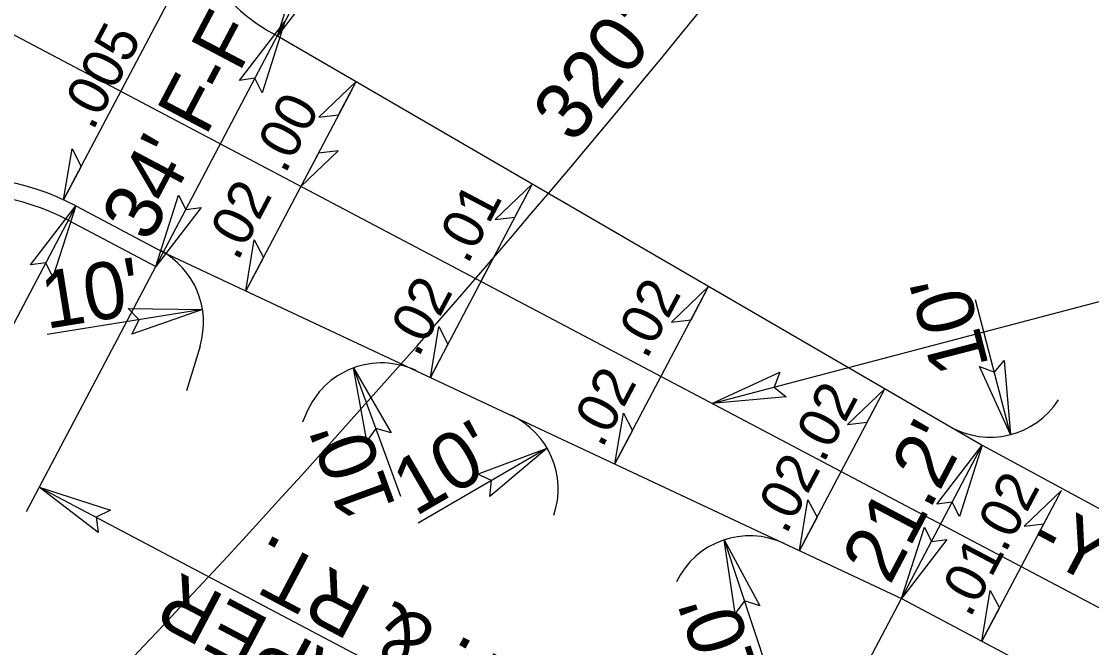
# Model space of a CAD drawing. Extents: x 2010838 to 2015151, y 441905 to 447792.
# Drawn here: x 2014224.3 to 2014355.7, y 445259 to 445335.9 of the extents above; entities that cross this region are included whole.
import ezdxf

# ---------------------------------------------------------------- set-up
doc = ezdxf.new("R2010")
doc.units = 0
for name, color, linetype in [('A-Wall-Blow', 7, 'Continuous'), ('A-Wall-Comp', 7, 'Continuous'), ('C-Building', 7, 'Continuous'), ('C-CURB STOPS', 7, 'Continuous'), ('C-Grave Plots', 7, 'Continuous'), ('CLRD', 7, 'Continuous'), ('Cont-2-Lidar', 7, 'Continuous'), ('DEED', 7, 'Continuous'), ('Default_10ft_LIDAR_Contou', 7, 'Continuous'), ('HATCH', 7, 'Continuous'), ('s-Existing Major', 7, 'Continuous'), ('S-Existing Minor', 7, 'Continuous'), ('S-overhead electric', 7, 'Continuous'), ('TEXT-MED', 7, 'Continuous')]:
    doc.layers.add(name, color=color, linetype=linetype)

msp = doc.modelspace()

# ---------------------------------------------------------------- linework, layer by layer
at = {"layer": 'A-Wall-Blow'}
for p, q in [((2014229.53, 445314), (2014245.5, 445344.26)), ((2014252.46, 445303.88), (2014264.98, 445327.61)), ((2014274.57, 445292.21), (2014287.09, 445315.94)), ((2014297.23, 445281.58), (2014308.73, 445303.38)), ((2014319.88, 445270.95), (2014330.36, 445290.81)), ((2014342.28, 445259.83), (2014352.04, 445278.32))]:
    msp.add_line(p, q, dxfattribs=at)
at = {"layer": 'A-Wall-Comp'}
for points in [[(2014265.45, 445328.51), (2014260.88, 445324.13), (2014263.29, 445324.42)], [(2014229.53, 445314), (2014230.56, 445320.24), (2014231.69, 445318.09)], [(2014258.66, 445315.64), (2014263.23, 445320.01), (2014260.82, 445319.73)], [(2014287.09, 445315.94), (2014282.52, 445311.57), (2014284.93, 445311.85)], [(2014251.91, 445302.84), (2014252.94, 445309.08), (2014254.07, 445306.93)], [(2014308.73, 445303.38), (2014304.16, 445299), (2014306.57, 445299.29)], [(2014274.57, 445292.21), (2014275.6, 445298.45), (2014276.72, 445296.3)], [(2014330.36, 445290.81), (2014325.79, 445286.44), (2014328.2, 445286.72)], [(2014297.23, 445281.58), (2014298.26, 445287.82), (2014299.38, 445285.67)], [(2014352.04, 445278.32), (2014347.47, 445273.94), (2014349.88, 445274.23)], [(2014319.88, 445270.95), (2014320.92, 445277.19), (2014322.04, 445275.04)], [(2014342.28, 445259.83), (2014343.31, 445266.07), (2014344.44, 445263.92)]]:
    msp.add_lwpolyline(points, close=True, dxfattribs=at)
at = {"layer": 'C-Building'}
msp.add_line((2014280.77, 445303.97), (2014283.11, 445308.39), dxfattribs=at)
at = {"layer": 'C-CURB STOPS'}
msp.add_arc((2013223.9, 446217.91), 1292, 312.84627, 322.2051, dxfattribs=at)
msp.add_arc((2013223.9, 446217.91), 1292, 312.84627, 322.2051, dxfattribs=at)
at = {"layer": 'C-Grave Plots'}
for p, q in [((2014345.79, 445285.19), (2014341.51, 445301.74)), ((2014246.59, 445300.55), (2014227.5, 445297.46)), ((2014265.14, 445293.37), (2014270.89, 445277.61)), ((2014288.89, 445283.53), (2014273.05, 445274.31)), ((2014310.65, 445272.27), (2014316.07, 445255.82))]:
    msp.add_line(p, q, dxfattribs=at)
at = {"layer": 'CLRD'}
msp.add_line((2014192.33, 445350.64), (2014369.92, 445256.93), dxfattribs=at)
msp.add_line((2014192.33, 445350.64), (2014369.92, 445256.93), dxfattribs=at)
msp.add_arc((2013223.9, 446217.91), 1300, 266.62643, 322.2051, dxfattribs=at)
at = {"layer": 'DEED'}
msp.add_arc((2013223.9, 446217.91), 1292, 312.84627, 322.2051, dxfattribs=at)
at = {"layer": 'Default_10ft_LIDAR_Contou'}
msp.add_line((2014309.14, 445289), (2014410.5, 445315.67), dxfattribs=at)
at = {"layer": 'HATCH'}
for radius, start in [(1279.25, 293.04012), (1291.25, 312.84627)]:
    msp.add_arc((2013223.9, 446217.91), radius, start, 322.2051, dxfattribs=at)
at = {"layer": 's-Existing Major'}
for points in [[(2014261.35, 445341.36), (2014255.78, 445334.12), (2014258.58, 445342.87), (2014259.46, 445341.11)], [(2014251.14, 445328.66), (2014256.71, 445335.89), (2014253.9, 445327.14), (2014253.02, 445328.91)], [(2014246.41, 445313.06), (2014240.84, 445305.82), (2014243.65, 445314.57), (2014244.53, 445312.81)], [(2014225.45, 445306.03), (2014231.02, 445313.26), (2014228.22, 445304.51), (2014227.34, 445306.28)], [(2014237.45, 445300.65), (2014246.59, 445300.55), (2014237.91, 445297.53), (2014238.79, 445299.29)], [(2014266.77, 445284.39), (2014265.14, 445293.37), (2014269.74, 445285.42), (2014267.85, 445285.95)], [(2014345.03, 445294.29), (2014345.79, 445285.19), (2014341.97, 445293.55), (2014343.81, 445292.84)], [(2014318.24, 445289.8), (2014309.14, 445289), (2014317.48, 445292.85), (2014316.78, 445291.01)], [(2014280.34, 445280.34), (2014288.89, 445283.53), (2014281.88, 445277.59), (2014282.07, 445279.55)], [(2014336.75, 445276.63), (2014342.32, 445283.87), (2014339.52, 445275.12), (2014338.64, 445276.88)], [(2014233.78, 445273.16), (2014226.54, 445278.73), (2014235.3, 445275.92), (2014233.53, 445275.04)], [(2014337.98, 445272.31), (2014332.41, 445265.08), (2014335.22, 445273.83), (2014336.1, 445272.07)], [(2014311.99, 445263.24), (2014310.65, 445272.27), (2014315, 445264.18), (2014313.12, 445264.77)]]:
    msp.add_lwpolyline(points, close=True, dxfattribs=at)
at = {"layer": 'S-Existing Minor'}
for p, q in [((2014255.78, 445334.12), (2014267.44, 445356.23)), ((2014240.84, 445305.82), (2014256.71, 445335.89)), ((2014231.02, 445313.26), (2014217.02, 445286.73)), ((2014224.97, 445275.75), (2014240.84, 445305.82)), ((2014332.41, 445265.08), (2014342.32, 445283.87)), ((2014226.54, 445278.73), (2014314.99, 445232.06)), ((2014313.69, 445229.61), (2014332.41, 445265.08))]:
    msp.add_line(p, q, dxfattribs=at)
msp.add_arc((2013223.9, 446217.91), 1396.5, 312.84627, 322.2051, dxfattribs=at)
at = {"layer": 'S-overhead electric'}
for p, q in [((2014255.78, 445334.12), (2014342.32, 445283.87)), ((2014231.02, 445313.26), (2014241.77, 445307.59)), ((2014241.77, 445307.59), (2014332.41, 445265.08)), ((2014246.28, 445296.05), (2014244.61, 445290.55)), ((2014259.34, 445287.85), (2014258.87, 445286.72)), ((2014342.32, 445283.87), (2014374.15, 445266.65)), ((2014332.41, 445265.08), (2014364.36, 445248.11))]:
    msp.add_line(p, q, dxfattribs=at)
for centre, radius, start, end in [((2014267.44, 445356.23), 25, 142.5158, 242.1794), ((2014217.02, 445286.73), 30, 62.1794, 138.8941), ((2014236.71, 445298.96), 10, 343.1231, 62.1794), ((2014268.57, 445283.98), 10, 64.8706, 157.2405), ((2014343.28, 445294.87), 10, 239.8564, 327.199), ((2014280.25, 445278.5), 10, 341.2682, 64.8706), ((2014313.78, 445262.77), 10, 64.8706, 154.1555)]:
    msp.add_arc(centre, radius, start, end, dxfattribs=at)
at = {"layer": 'TEXT-MED'}
msp.add_line((2014230.09, 445311.5), (2014240.84, 445305.82), dxfattribs=at)
msp.add_arc((2014217.02, 445286.73), 28, 62.1794, 138.8941, dxfattribs=at)

# ---------------------------------------------------------------- texts
at = {"layer": 'A-Wall-Blow'}
for s, p in [('.005', (2014233.11, 445322.36)), ('.00', (2014256.72, 445317.06)), ('.02', (2014250.89, 445306.36)), ('.01', (2014279.12, 445305.96)), ('.02', (2014273.07, 445294.53)), ('.02', (2014301.1, 445294.29)), ('.02', (2014295.65, 445283.4)), ('.02', (2014322.84, 445281.57)), ('.02', (2014318.23, 445272.8)), ('.02', (2014345.15, 445270.54)), ('.01', (2014340.82, 445262.57))]:
    msp.add_text(s, height=5, rotation=62.1794, dxfattribs=at).set_placement(p)
at = {"layer": 'C-Grave Plots'}
for s, rotation, p in [("320' MEDIAN TAPER", 51.6129, (2014292.15, 445320.73)), ("34' F-F", 62.1794, (2014240.06, 445308.59)), ("10'", 9.2014, (2014227.4, 445298.14)), ("10'", 104.4932, (2014343.16, 445293.6)), ("10'", 30.1927, (2014272.7, 445275.07)), ("21.2'", 62.1794, (2014330.98, 445266.6)), ("10'", 110.0326, (2014270.37, 445276.37)), ('LT. & RT.', 152.1794, (2014289.82, 445254.4)), ("100' TAPER", 152.1794, (2014288.89, 445244.52)), ("10'", 108.2402, (2014315.37, 445254.8))]:
    msp.add_text(s, height=7, rotation=rotation, dxfattribs=at).set_placement(p)
at = {"layer": 'Cont-2-Lidar'}
msp.add_text('-Y4-', height=7, rotation=332.1794, dxfattribs=at).set_placement((2014347.61, 445271.04))

doc.saveas('drawing.dxf')
